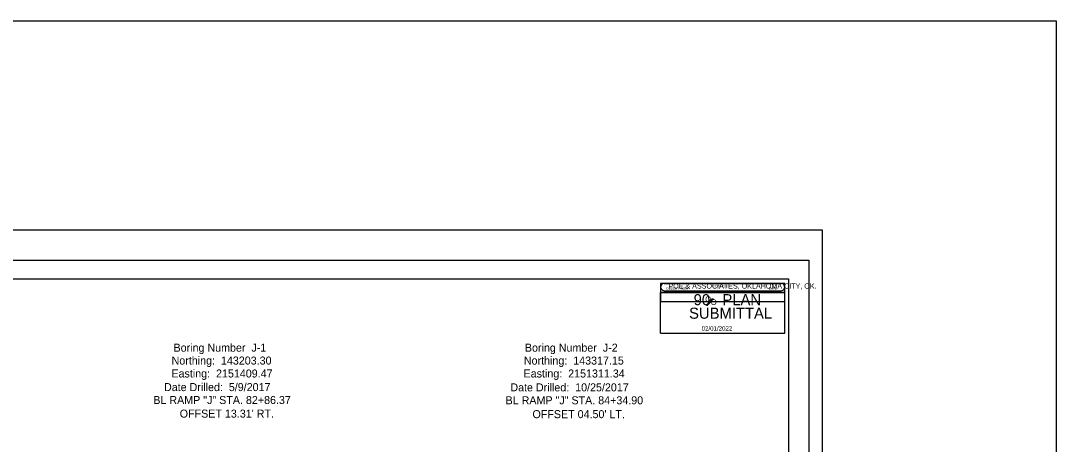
# Model space of a CAD drawing. Extents: x 2150148.6 to 2150220.1, y 143803.7 to 143875.1.
# Drawn here: x 2150182.61 to 2150220.06, y 143859.84 to 143875.14 of the extents above; entities that cross this region are included whole.
import ezdxf

# ---------------------------------------------------------------- set-up
doc = ezdxf.new("R2010")
doc.units = 0
for name, color, linetype in [('Default', 7, 'Continuous'), ('S', 7, 'Continuous'), ('SHT_Plot_Shape_Full', 7, 'Continuous'), ('SHT_Plot_Shape_Half', 7, 'Continuous'), ('SHT_Sheet_Border', 7, 'Continuous'), ('SHT_Stamp_90_Submit', 7, 'Continuous'), ('SHT_Stamp_Rev_Block', 7, 'Continuous'), ('SHT_Stamp_Rev_Prop_RW', 7, 'Continuous')]:
    doc.layers.add(name, color=color, linetype=linetype)

msp = doc.modelspace()

# ---------------------------------------------------------------- linework, layer by layer
at = {"layer": 'S'}
msp.add_lwpolyline([(2150160.321, 143875.14), (2150220.06, 143875.14), (2150220.06, 143803.708), (2150160.321, 143803.708)], close=True, dxfattribs=at)
at = {"layer": 'SHT_Plot_Shape_Full'}
msp.add_lwpolyline([(2150163.596, 143867.587), (2150211.596, 143867.587), (2150211.596, 143835.587), (2150163.596, 143835.587)], close=True, dxfattribs=at)
at = {"layer": 'SHT_Plot_Shape_Half'}
msp.add_lwpolyline([(2150165.779, 143866.487), (2150211.112, 143866.487), (2150211.112, 143837.154), (2150165.779, 143837.154)], close=True, dxfattribs=at)
at = {"layer": 'SHT_Sheet_Border'}
msp.add_lwpolyline([(2150210.379, 143837.82), (2150168.379, 143837.82), (2150168.379, 143865.82), (2150210.379, 143865.82)], close=True, dxfattribs=at)
at = {"layer": 'SHT_Stamp_90_Submit'}
for p, q in [((2150205.887, 143865.655), (2150210.108, 143865.655)), ((2150205.887, 143865.388), (2150210.108, 143865.388)), ((2150205.754, 143865.321), (2150210.241, 143865.321)), ((2150205.754, 143863.856), (2150205.754, 143865.321)), ((2150207.411, 143864.87), (2150207.619, 143865.101)), ((2150207.435, 143864.87), (2150207.642, 143865.101)), ((2150207.442, 143864.87), (2150207.649, 143865.101)), ((2150207.452, 143864.87), (2150207.659, 143865.101)), ((2150207.619, 143865.101), (2150207.659, 143865.101)), ((2150210.241, 143863.856), (2150210.241, 143865.321)), ((2150207.411, 143864.87), (2150207.452, 143864.87)), ((2150205.754, 143863.856), (2150210.241, 143863.856))]:
    msp.add_line(p, q, dxfattribs=at)
for centre, start, end in [((2150205.887, 143865.522), 89.9952, 270), ((2150210.109, 143865.522), 270, 90.0048)]:
    msp.add_arc(centre, 0.133, start, end, dxfattribs=at)
at = {"layer": 'SHT_Stamp_Rev_Block'}
for p, q in [((2150205.754, 143865.655), (2150205.754, 143864.988)), ((2150210.241, 143865.655), (2150205.754, 143865.655)), ((2150210.241, 143864.988), (2150210.241, 143865.655)), ((2150210.241, 143865.321), (2150205.754, 143865.321)), ((2150210.241, 143864.988), (2150205.754, 143864.988))]:
    msp.add_line(p, q, dxfattribs=at)

# ---------------------------------------------------------------- texts
at = {"layer": 'Default'}
for s, p in [('Boring Number  J-1', (2150188.14, 143863.187)), ('Boring Number  J-2', (2150200.845, 143863.187)), ('Northing:  143203.30', (2150188.07, 143862.721)), ('Northing:  143317.15', (2150200.808, 143862.721)), ('Easting:  2151409.47', (2150188.064, 143862.254)), ('Easting:  2151311.34', (2150200.797, 143862.254)), ('Date Drilled:  5/9/2017', (2150187.796, 143861.763)), ('Date Drilled:  10/25/2017', (2150200.319, 143861.753)), ('BL RAMP "J" STA. 82+86.37', (2150187.409, 143861.296)), ('BL RAMP "J" STA. 84+34.90', (2150200.147, 143861.286)), ("OFFSET 13.31' RT.", (2150188.365, 143860.805)), ("OFFSET 04.50' LT.", (2150201.119, 143860.785))]:
    msp.add_text(s, height=0.28933, dxfattribs=at).set_placement(p)
at = {"layer": 'SHT_Stamp_90_Submit'}
for s, height, p in [('POE & ASSOCIATES, OKLAHOMA CITY, OK.', 0.18667, (2150206.034, 143865.465)), ('90   PLAN', 0.4, (2150206.947, 143864.865)), ('O', 0.204, (2150207.365, 143864.984)), ('O', 0.204, (2150207.568, 143864.871)), ('SUBMITTAL', 0.4, (2150206.782, 143864.377))]:
    msp.add_text(s, height=height, dxfattribs=at).set_placement(p)
at = {"layer": 'SHT_Stamp_Rev_Block'}
for s, height, p in [('DESCRIPTION', 0.07999, (2150205.967, 143865.426)), ('REVISIONS', 0.08, (2150207.631, 143865.505)), ('DATE', 0.08, (2150209.66, 143865.431))]:
    msp.add_text(s, height=height, dxfattribs=at).set_placement(p)
at = {"layer": 'SHT_Stamp_Rev_Prop_RW'}
msp.add_text('02/01/2022', height=0.16, dxfattribs=at).set_placement((2150207.238, 143863.947))

doc.saveas('drawing.dxf')
